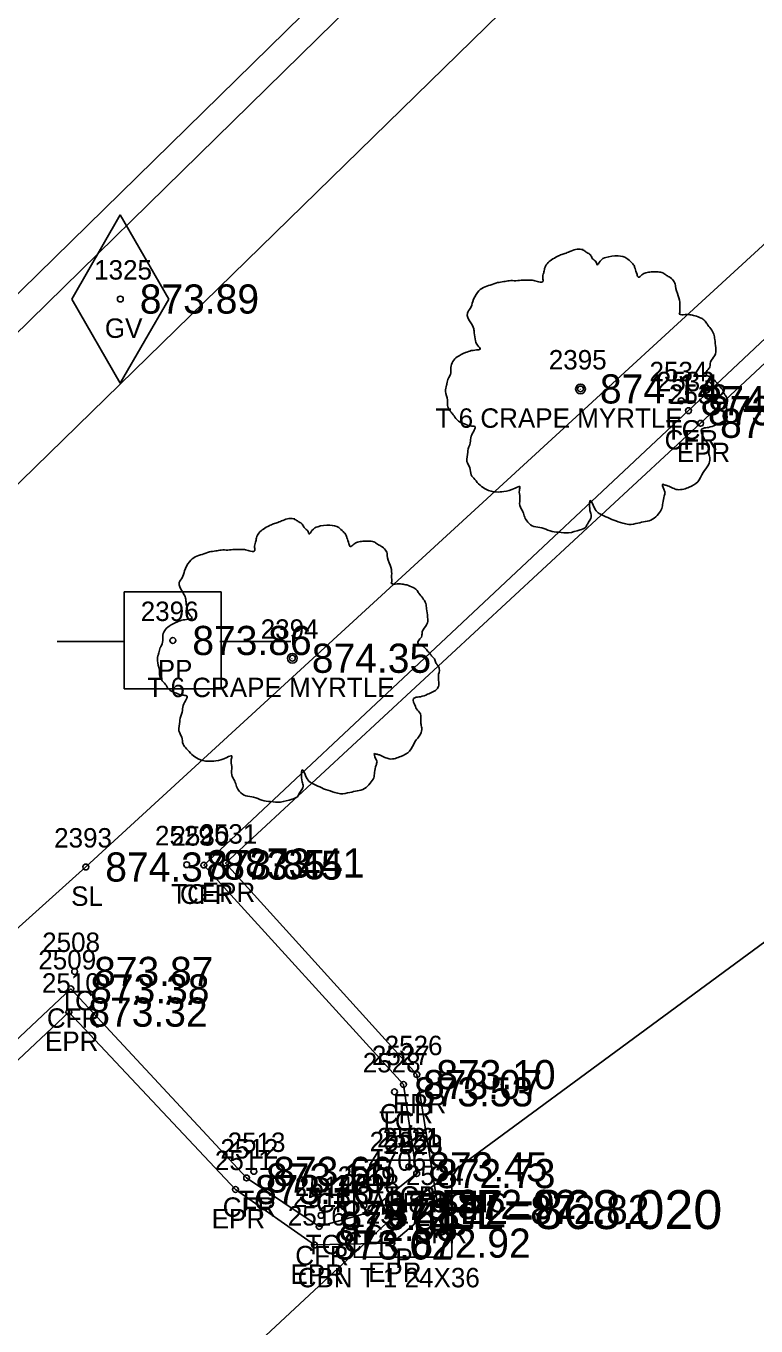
# Model space of a CAD drawing. Extents: x 1622501 to 1626664, y 1117816 to 1121579.
# Drawn here: x 1623806.5 to 1623844.1, y 1119016.9 to 1119083.8 of the extents above; entities that cross this region are included whole.
import ezdxf

# ---------------------------------------------------------------- set-up
doc = ezdxf.new("R2010")
doc.units = 0
for name, color, linetype in [('RD_EX_Conc', 7, 'Continuous'), ('RD_EX_Conc_txCode', 7, 'Continuous'), ('RD_EX_DR_Inlet', 7, 'Continuous'), ('RD_EX_DR_Inlet_txCode', 7, 'Continuous'), ('RD_EX_DR_Pipe', 7, 'Continuous'), ('RD_EX_DR_Pipe_txCode', 7, 'Continuous'), ('RD_EX_Road', 7, 'Continuous'), ('RD_EX_Road_txCode', 7, 'Continuous'), ('RD_EX_TX_Conc_ELEV', 7, 'Continuous'), ('RD_EX_TX_DR_Inlet_ELEV', 7, 'Continuous'), ('RD_EX_TX_Road_ELEV', 7, 'Continuous'), ('RD_EX_TX_UT_ELEV', 7, 'Continuous'), ('RD_EX_TX_VEG_ELEV', 7, 'Continuous'), ('RD_EX_UT', 7, 'Continuous'), ('RD_EX_UT_txCode', 7, 'Continuous'), ('RD_EX_VEG', 7, 'Continuous'), ('RD_EX_VEG_txCode', 7, 'Continuous'), ('RD_HC_Survey_ELEV', 7, 'Continuous'), ('RD_SMD_Locator', 7, 'Continuous'), ('RD_TX_Pipe_ElevEX', 7, 'Continuous')]:
    doc.layers.add(name, color=color, linetype=linetype)

msp = doc.modelspace()

# ---------------------------------------------------------------- linework, layer by layer
at = {"layer": 'RD_EX_Conc'}
for points in [[(1623723.663, 1118851.276), (1623685.686, 1118891.781), (1623680.278, 1118899.276), (1623678.543, 1118902.667), (1623678.543, 1118902.667), (1623675.573, 1118911.952), (1623675.054, 1118920.354), (1623676.566, 1118930.331), (1623679.225, 1118937.184), (1623684.435, 1118944.641), (1623689.976, 1118950.418), (1623724.501, 1118984.8), (1623759.009, 1119020.42), (1623793.698, 1119055.906), (1623829.35, 1119090.862), (1623865.612, 1119125.129), (1623901.916, 1119159.181), (1623933.224, 1119188.498)], [(1623676.299, 1118912.014), (1623681.213, 1118913.011), (1623680.576, 1118920.41), (1623681.86, 1118928.773), (1623684.243, 1118934.734), (1623688.548, 1118940.788), (1623694.147, 1118946.67), (1623728.265, 1118980.628), (1623762.622, 1119016.068), (1623797.565, 1119051.919), (1623833.104, 1119086.631), (1623869.148, 1119120.8), (1623905.547, 1119154.999), (1623936.969, 1119184.346), (1623933.79, 1119188.026)], [(1623776.374, 1119003.735), (1623808.841, 1119034.289), (1623817.882, 1119024.564), (1623821.612, 1119022.069), (1623824.094, 1119022.765), (1623826.626, 1119024.788), (1623826.626, 1119024.788), (1623825.953, 1119029.369), (1623815.684, 1119040.66), (1623840.6, 1119064.039), (1623868.084, 1119089.909)]]:
    msp.add_lwpolyline(points, dxfattribs=at)
at = {"layer": 'RD_EX_DR_Inlet'}
msp.add_line((1623828.428, 1119020.482), (1623828.428, 1119025.482), dxfattribs=at)
msp.add_lwpolyline([(1623828.428, 1119020.482), (1623828.428, 1119025.482), (1623823.428, 1119025.482), (1623823.428, 1119020.482)], close=True, dxfattribs=at)
at = {"layer": 'RD_EX_DR_Pipe'}
msp.add_lwpolyline([(1623764.491, 1118919.853), (1623773.64, 1118974.335), (1623825.837, 1119022.936), (1623907.44, 1119083.04), (1623936.884, 1119056.765)], dxfattribs=at)
at = {"layer": 'RD_EX_Road'}
for points in [[(1623722.97, 1118850.612), (1623684.945, 1118891.225), (1623679.413, 1118898.675), (1623674.261, 1118911.526), (1623673.503, 1118920.185), (1623675.206, 1118930.826), (1623677.985, 1118937.822), (1623683.61, 1118945.518), (1623688.806, 1118951.265), (1623723.469, 1118985.717), (1623758.003, 1119021.43), (1623792.693, 1119056.92), (1623828.408, 1119091.915), (1623864.599, 1119126.191), (1623900.882, 1119160.216), (1623932.37, 1119189.416), (1623932.628, 1119189.219), (1623935.818, 1119192.17), (1623973.771, 1119227.767), (1623990.875, 1119243.538), (1624009.987, 1119262.018), (1624046.295, 1119296.153)], [(1623776.805, 1119003.039), (1623808.744, 1119033.096), (1623817.315, 1119023.967), (1623821.371, 1119021.115), (1623825.354, 1119021.212), (1623827.704, 1119023.202), (1623826.634, 1119029.88), (1623816.804, 1119040.763), (1623841.225, 1119063.389), (1623868.182, 1119088.58)]]:
    msp.add_lwpolyline(points, dxfattribs=at)
at = {"layer": 'RD_EX_UT'}
for p, q in [((1623808.89, 1119069.782), (1623811.39, 1119074.112)), ((1623811.39, 1119074.112), (1623813.89, 1119069.782)), ((1623808.89, 1119069.782), (1623811.39, 1119065.452)), ((1623811.39, 1119065.452), (1623813.89, 1119069.782)), ((1623816.582, 1119054.725), (1623811.582, 1119054.725)), ((1623811.582, 1119054.725), (1623811.582, 1119049.725)), ((1623816.582, 1119049.725), (1623816.582, 1119054.725)), ((1623808.151, 1119052.163), (1623811.621, 1119052.163)), ((1623816.511, 1119052.163), (1623820.151, 1119052.163)), ((1623811.582, 1119049.725), (1623816.582, 1119049.725))]:
    msp.add_line(p, q, dxfattribs=at)
at = {"layer": 'RD_EX_VEG'}
msp.add_lwpolyline([(1623719.641, 1118895.843), (1623705.963, 1118915.58), (1623701.704, 1118941.089), (1623733.735, 1118974.045), (1623762.596, 1118998.968), (1623764.149, 1118997.606), (1623773.667, 1119008.214), (1623809.616, 1119040.562), (1623866.904, 1119093.207), (1623868.266, 1119096.09), (1623881.794, 1119107.882), (1623919.645, 1119143.849), (1623945.126, 1119165.729), (1623961.583, 1119122.835), (1623970.119, 1119088.038)], dxfattribs=at)
for centre, radius in [((1623835.049, 1119065.157), 0.25), ((1623835.037, 1119065.138), 0.0001), ((1623820.236, 1119051.301), 0.25), ((1623820.223, 1119051.282), 0.0001)]:
    msp.add_circle(centre, radius, dxfattribs=at)
for points in [[(1623835.181, 1119072.324), (1623834.881, 1119072.349), (1623834.557, 1119072.249), (1623834.307, 1119072.149), (1623834.082, 1119072.074), (1623833.857, 1119071.974), (1623833.557, 1119071.799), (1623833.332, 1119071.599), (1623833.207, 1119071.349), (1623833.157, 1119071.124), (1623833.107, 1119070.85), (1623833.107, 1119070.675), (1623832.982, 1119070.65), (1623832.832, 1119070.675), (1623832.582, 1119070.75), (1623832.333, 1119070.75), (1623832.083, 1119070.75), (1623831.733, 1119070.725), (1623831.383, 1119070.725), (1623831.108, 1119070.675), (1623830.783, 1119070.625), (1623830.408, 1119070.5), (1623830.059, 1119070.375), (1623829.759, 1119070.125), (1623829.509, 1119069.65), (1623829.384, 1119069.3), (1623829.234, 1119069.05), (1623829.384, 1119068.601), (1623829.559, 1119068.251), (1623829.584, 1119068.051), (1623829.659, 1119067.626), (1623829.759, 1119067.401), (1623829.884, 1119067.201), (1623829.809, 1119067.176), (1623829.434, 1119067.126), (1623829.134, 1119067.026), (1623828.709, 1119066.801), (1623828.484, 1119066.576), (1623828.384, 1119066.251), (1623828.359, 1119065.902), (1623828.259, 1119065.702), (1623828.184, 1119065.427), (1623828.159, 1119065.352), (1623828.109, 1119065.027), (1623828.209, 1119064.577), (1623828.234, 1119064.227), (1623828.359, 1119064.002), (1623828.509, 1119063.828), (1623828.684, 1119063.578), (1623829.084, 1119063.353), (1623829.409, 1119063.253), (1623829.609, 1119063.228), (1623829.434, 1119062.728), (1623829.384, 1119062.378), (1623829.259, 1119061.978), (1623829.259, 1119061.903), (1623829.209, 1119061.429), (1623829.359, 1119061.104), (1623829.434, 1119060.729), (1623829.609, 1119060.504), (1623829.884, 1119060.204), (1623830.208, 1119059.979), (1623830.708, 1119059.854), (1623831.108, 1119059.879), (1623831.683, 1119060.054), (1623831.933, 1119060.129), (1623831.908, 1119059.954), (1623831.933, 1119059.579), (1623831.933, 1119059.155), (1623832.083, 1119058.83), (1623832.183, 1119058.555), (1623832.333, 1119058.305), (1623832.657, 1119058.08), (1623833.057, 1119058.005), (1623833.482, 1119057.855), (1623833.932, 1119057.78), (1623834.432, 1119057.755), (1623835.031, 1119057.905), (1623835.306, 1119058.03), (1623835.406, 1119058.205), (1623835.606, 1119058.58), (1623835.556, 1119058.805), (1623835.581, 1119059.405), (1623835.681, 1119059.23), (1623835.856, 1119058.88), (1623836.356, 1119058.58), (1623836.756, 1119058.405), (1623837.23, 1119058.255), (1623837.53, 1119058.18), (1623838.005, 1119058.255), (1623838.38, 1119058.33), (1623838.755, 1119058.455), (1623839.055, 1119058.73), (1623839.23, 1119059.005), (1623839.28, 1119059.28), (1623839.354, 1119059.654), (1623839.404, 1119059.829)], [(1623839.404, 1119059.829), (1623839.33, 1119060.004), (1623839.28, 1119060.254), (1623839.354, 1119060.229), (1623839.529, 1119060.179), (1623839.804, 1119060.054), (1623840.029, 1119059.979), (1623840.354, 1119060.004), (1623840.629, 1119060.104), (1623841.079, 1119060.379), (1623841.354, 1119060.854), (1623841.628, 1119061.254), (1623841.703, 1119061.579), (1623841.653, 1119061.803), (1623841.628, 1119062.303), (1623841.429, 1119062.553), (1623841.379, 1119062.678), (1623841.279, 1119063.078), (1623841.354, 1119063.128), (1623841.628, 1119063.178), (1623842.003, 1119063.303), (1623842.278, 1119063.428), (1623842.503, 1119063.603), (1623842.578, 1119063.828), (1623842.553, 1119064.227), (1623842.603, 1119064.627), (1623842.528, 1119064.777), (1623842.428, 1119064.927), (1623842.353, 1119065.127), (1623842.203, 1119065.277), (1623842.103, 1119065.427), (1623842.003, 1119065.527), (1623841.878, 1119065.677), (1623841.703, 1119065.802), (1623841.554, 1119065.852), (1623841.504, 1119066.002), (1623841.653, 1119066.202), (1623841.703, 1119066.301), (1623841.728, 1119066.526), (1623841.953, 1119066.876), (1623842.003, 1119067.276), (1623841.953, 1119067.701), (1623841.903, 1119067.976), (1623841.753, 1119068.251), (1623841.554, 1119068.501), (1623841.429, 1119068.675), (1623841.254, 1119068.8), (1623840.929, 1119068.925), (1623840.679, 1119068.975), (1623840.329, 1119068.975), (1623840.129, 1119069.025), (1623840.154, 1119069.075), (1623840.154, 1119069.225), (1623840.154, 1119069.5), (1623840.079, 1119069.95), (1623839.929, 1119070.45), (1623839.929, 1119070.475), (1623839.829, 1119070.725), (1623839.604, 1119070.924), (1623839.429, 1119071.024), (1623839.23, 1119071.149), (1623838.98, 1119071.174), (1623838.68, 1119071.174), (1623838.405, 1119071.124), (1623838.205, 1119071.024), (1623838.03, 1119070.899), (1623837.955, 1119071.049), (1623837.855, 1119071.349), (1623837.805, 1119071.499), (1623837.655, 1119071.674), (1623837.43, 1119071.874), (1623836.98, 1119071.999), (1623836.356, 1119071.924), (1623836.056, 1119071.724), (1623835.906, 1119071.549), (1623835.856, 1119071.674), (1623835.656, 1119071.874), (1623835.556, 1119072.049), (1623835.381, 1119072.174), (1623835.231, 1119072.274), (1623835.131, 1119072.324)], [(1623820.368, 1119058.468), (1623820.068, 1119058.493), (1623819.743, 1119058.393), (1623819.493, 1119058.293), (1623819.268, 1119058.218), (1623819.044, 1119058.118), (1623818.744, 1119057.944), (1623818.519, 1119057.744), (1623818.394, 1119057.494), (1623818.344, 1119057.269), (1623818.294, 1119056.994), (1623818.294, 1119056.819), (1623818.169, 1119056.794), (1623818.019, 1119056.819), (1623817.769, 1119056.894), (1623817.519, 1119056.894), (1623817.269, 1119056.894), (1623816.919, 1119056.869), (1623816.57, 1119056.869), (1623816.295, 1119056.819), (1623815.97, 1119056.769), (1623815.595, 1119056.644), (1623815.245, 1119056.519), (1623814.945, 1119056.269), (1623814.695, 1119055.795), (1623814.57, 1119055.445), (1623814.421, 1119055.195), (1623814.57, 1119054.745), (1623814.745, 1119054.395), (1623814.77, 1119054.195), (1623814.845, 1119053.77), (1623814.945, 1119053.546), (1623815.07, 1119053.346), (1623814.995, 1119053.321), (1623814.62, 1119053.271), (1623814.321, 1119053.171), (1623813.896, 1119052.946), (1623813.671, 1119052.721), (1623813.571, 1119052.396), (1623813.546, 1119052.046), (1623813.446, 1119051.846), (1623813.371, 1119051.571), (1623813.346, 1119051.496), (1623813.296, 1119051.172), (1623813.396, 1119050.722), (1623813.421, 1119050.372), (1623813.546, 1119050.147), (1623813.696, 1119049.972), (1623813.871, 1119049.722), (1623814.271, 1119049.497), (1623814.595, 1119049.397), (1623814.795, 1119049.372), (1623814.62, 1119048.873), (1623814.57, 1119048.523), (1623814.446, 1119048.123), (1623814.446, 1119048.048), (1623814.396, 1119047.573), (1623814.545, 1119047.248), (1623814.62, 1119046.873), (1623814.795, 1119046.649), (1623815.07, 1119046.349), (1623815.395, 1119046.124), (1623815.895, 1119045.999), (1623816.295, 1119046.024), (1623816.87, 1119046.199), (1623817.119, 1119046.274), (1623817.094, 1119046.099), (1623817.119, 1119045.724), (1623817.119, 1119045.299), (1623817.269, 1119044.974), (1623817.369, 1119044.699), (1623817.519, 1119044.449), (1623817.844, 1119044.225), (1623818.244, 1119044.15), (1623818.669, 1119044), (1623819.119, 1119043.925), (1623819.618, 1119043.9), (1623820.218, 1119044.05), (1623820.493, 1119044.175), (1623820.593, 1119044.35), (1623820.793, 1119044.724), (1623820.743, 1119044.949), (1623820.768, 1119045.549), (1623820.868, 1119045.374), (1623821.043, 1119045.024), (1623821.542, 1119044.724), (1623821.942, 1119044.549), (1623822.417, 1119044.399), (1623822.717, 1119044.325), (1623823.192, 1119044.399), (1623823.567, 1119044.474), (1623823.941, 1119044.599), (1623824.241, 1119044.874), (1623824.416, 1119045.149), (1623824.466, 1119045.424), (1623824.541, 1119045.799), (1623824.591, 1119045.974)], [(1623824.591, 1119045.974), (1623824.516, 1119046.149), (1623824.466, 1119046.399), (1623824.541, 1119046.374), (1623824.716, 1119046.324), (1623824.991, 1119046.199), (1623825.216, 1119046.124), (1623825.541, 1119046.149), (1623825.816, 1119046.249), (1623826.265, 1119046.524), (1623826.54, 1119046.998), (1623826.815, 1119047.398), (1623826.89, 1119047.723), (1623826.84, 1119047.948), (1623826.815, 1119048.448), (1623826.615, 1119048.698), (1623826.565, 1119048.823), (1623826.465, 1119049.222), (1623826.54, 1119049.272), (1623826.815, 1119049.322), (1623827.19, 1119049.447), (1623827.465, 1119049.572), (1623827.69, 1119049.747), (1623827.765, 1119049.972), (1623827.74, 1119050.372), (1623827.79, 1119050.772), (1623827.715, 1119050.922), (1623827.615, 1119051.072), (1623827.54, 1119051.272), (1623827.39, 1119051.421), (1623827.29, 1119051.571), (1623827.19, 1119051.671), (1623827.065, 1119051.821), (1623826.89, 1119051.946), (1623826.74, 1119051.996), (1623826.69, 1119052.146), (1623826.84, 1119052.346), (1623826.89, 1119052.446), (1623826.915, 1119052.671), (1623827.14, 1119053.021), (1623827.19, 1119053.421), (1623827.14, 1119053.845), (1623827.09, 1119054.12), (1623826.94, 1119054.395), (1623826.74, 1119054.645), (1623826.615, 1119054.82), (1623826.44, 1119054.945), (1623826.115, 1119055.07), (1623825.866, 1119055.12), (1623825.516, 1119055.12), (1623825.316, 1119055.17), (1623825.341, 1119055.22), (1623825.341, 1119055.37), (1623825.341, 1119055.645), (1623825.266, 1119056.094), (1623825.116, 1119056.594), (1623825.116, 1119056.619), (1623825.016, 1119056.869), (1623824.791, 1119057.069), (1623824.616, 1119057.169), (1623824.416, 1119057.294), (1623824.166, 1119057.319), (1623823.866, 1119057.319), (1623823.592, 1119057.269), (1623823.392, 1119057.169), (1623823.217, 1119057.044), (1623823.142, 1119057.194), (1623823.042, 1119057.494), (1623822.992, 1119057.644), (1623822.842, 1119057.819), (1623822.617, 1119058.019), (1623822.167, 1119058.143), (1623821.542, 1119058.069), (1623821.243, 1119057.869), (1623821.093, 1119057.694), (1623821.043, 1119057.819), (1623820.843, 1119058.019), (1623820.743, 1119058.193), (1623820.568, 1119058.318), (1623820.418, 1119058.418), (1623820.318, 1119058.468)]]:
    msp.add_spline(points, degree=3, dxfattribs=at)
at = {"layer": 'RD_SMD_Locator'}
for centre, radius in [((1623811.39, 1119069.782), 0.15), ((1623835.049, 1119065.157), 0.15), ((1623840.227, 1119064.551), 0.15), ((1623840.6, 1119064.039), 0.15), ((1623841.225, 1119063.389), 0.15), ((1623814.092, 1119052.216), 0.15), ((1623820.236, 1119051.301), 0.15), ((1623809.616, 1119040.562), 0.15), ((1623814.802, 1119040.678), 0.15), ((1623815.684, 1119040.66), 0.15), ((1623816.804, 1119040.763), 0.15), ((1623809.041, 1119035.189), 0.15), ((1623808.841, 1119034.289), 0.15), ((1623808.744, 1119033.096), 0.15), ((1623826.634, 1119029.88), 0.15), ((1623825.483, 1119028.995), 0.15), ((1623825.953, 1119029.369), 0.15), ((1623818.252, 1119024.901), 0.15), ((1623826.222, 1119025.136), 0.15), ((1623826.222, 1119025.136), 0.15), ((1623817.882, 1119024.564), 0.15), ((1623826.626, 1119024.788), 0.15), ((1623826.626, 1119024.788), 0.15), ((1623817.315, 1119023.967), 0.15), ((1623823.912, 1119023.156), 0.15), ((1623825.837, 1119022.936), 0.2), ((1623825.837, 1119022.936), 0.15), ((1623827.704, 1119023.202), 0.15), ((1623821.71, 1119022.638), 0.15), ((1623824.094, 1119022.765), 0.15), ((1623821.612, 1119022.069), 0.15), ((1623821.371, 1119021.115), 0.15), ((1623825.354, 1119021.212), 0.15)]:
    msp.add_circle(centre, radius, dxfattribs=at)

# ---------------------------------------------------------------- texts
at = {"layer": 'RD_EX_Conc_txCode'}
for s, p in [('2534', (1623838.597, 1119065.551)), ('2533', (1623838.97, 1119065.039)), ('TC', (1623839.432, 1119062.551)), ('CFR', (1623839.372, 1119062.039)), ('2529', (1623813.172, 1119041.678)), ('2530', (1623814.015, 1119041.66)), ('TC', (1623814.006, 1119038.678)), ('CFR', (1623814.456, 1119038.66)), ('2508', (1623807.372, 1119036.189)), ('2509', (1623807.172, 1119035.289)), ('TC', (1623808.246, 1119033.189)), ('CFR', (1623807.613, 1119032.289)), ('2527', (1623824.323, 1119030.369)), ('2528', (1623823.853, 1119029.995)), ('CFR', (1623824.724, 1119027.369)), ('TC', (1623824.687, 1119026.995)), ('2522', (1623824.592, 1119026.136)), ('2521', (1623824.875, 1119026.136)), ('2512', (1623816.536, 1119025.564)), ('2513', (1623816.906, 1119025.901)), ('2520', (1623824.957, 1119025.788)), ('2523', (1623824.996, 1119025.788)), ('2519', (1623822.565, 1119024.156)), ('2514', (1623820.364, 1119023.638)), ('2518', (1623822.748, 1119023.765)), ('TC', (1623817.457, 1119022.901)), ('2515', (1623820.266, 1119023.069)), ('CFRA 18 CONC', (1623821.453, 1119022.788)), ('TCA', (1623824.938, 1119023.136)), ('TCB', (1623824.954, 1119023.136)), ('CFRB', (1623824.926, 1119022.788)), ('CFR', (1623816.654, 1119022.564)), ('CFR', (1623822.866, 1119020.765)), ('TC', (1623823.116, 1119021.156)), ('CFR', (1623820.384, 1119020.069)), ('TC', (1623820.915, 1119020.638))]:
    msp.add_text(s, height=1, dxfattribs=at).set_placement(p)
at = {"layer": 'RD_EX_DR_Inlet_txCode'}
for s, p in [('2525', (1623824.207, 1119025.936)), ('CBN T 1 24X36', (1623820.506, 1119018.936))]:
    msp.add_text(s, height=1, dxfattribs=at).set_placement(p)
at = {"layer": 'RD_EX_DR_Pipe_txCode'}
for s, p in [('4706', (1623824.144, 1119024.936)), ('P', (1623825.53, 1119019.936))]:
    msp.add_text(s, height=1, dxfattribs=at).set_placement(p)
at = {"layer": 'RD_EX_Road_txCode'}
for s, p in [('2532', (1623839.595, 1119064.389)), ('EPR', (1623839.997, 1119061.389)), ('2531', (1623815.458, 1119041.763)), ('EPR', (1623815.576, 1119038.763)), ('2510', (1623807.358, 1119034.096)), ('EPR', (1623807.515, 1119031.096)), ('2526', (1623824.98, 1119030.88)), ('EPR', (1623825.405, 1119027.88)), ('2511', (1623816.252, 1119024.967)), ('2524', (1623826.074, 1119024.202)), ('2516', (1623820, 1119022.115)), ('2517', (1623824.008, 1119022.212)), ('EPR', (1623816.087, 1119021.967)), ('EPR', (1623826.475, 1119021.202)), ('EPR', (1623820.142, 1119019.115)), ('EPR', (1623824.126, 1119019.212))]:
    msp.add_text(s, height=1, dxfattribs=at).set_placement(p)
at = {"layer": 'RD_EX_TX_Conc_ELEV'}
for s, p in [('874.21', (1623841.227, 1119063.801)), ('873.73', (1623841.6, 1119063.289)), ('873.85', (1623815.802, 1119039.928)), ('873.45', (1623816.684, 1119039.91)), ('873.87', (1623810.041, 1119034.439)), ('873.38', (1623809.841, 1119033.539)), ('873.53', (1623826.483, 1119028.245)), ('873.07', (1623826.953, 1119028.619)), ('873.45', (1623827.222, 1119024.386)), ('873.45', (1623827.222, 1119024.386)), ('873.16', (1623818.882, 1119023.814)), ('873.66', (1623819.252, 1119024.151)), ('872.73', (1623827.626, 1119024.038)), ('872.73', (1623827.626, 1119024.038)), ('873.47', (1623824.912, 1119022.406)), ('873.48', (1623822.71, 1119021.888)), ('872.72', (1623825.094, 1119022.015)), ('872.98', (1623822.612, 1119021.319))]:
    msp.add_text(s, height=1.5, dxfattribs=at).set_placement(p)
at = {"layer": 'RD_EX_TX_DR_Inlet_ELEV'}
msp.add_text('EL=872.82', height=1.5, dxfattribs=at).set_placement((1623828.837, 1119022.186))
at = {"layer": 'RD_EX_TX_Road_ELEV'}
for s, p in [('873.73', (1623842.225, 1119062.639)), ('873.41', (1623817.804, 1119040.013)), ('873.32', (1623809.744, 1119032.346)), ('873.10', (1623827.634, 1119029.13)), ('873.16', (1623818.315, 1119023.217)), ('872.92', (1623828.704, 1119022.452)), ('873.02', (1623822.371, 1119020.365)), ('872.92', (1623826.354, 1119020.462))]:
    msp.add_text(s, height=1.5, dxfattribs=at).set_placement(p)
at = {"layer": 'RD_EX_TX_UT_ELEV'}
msp.add_text('873.89', height=1.5, dxfattribs=at).set_placement((1623812.39, 1119069.032))
at = {"layer": 'RD_EX_TX_VEG_ELEV'}
for s, p in [('874.14', (1623836.049, 1119064.407)), ('874.35', (1623821.236, 1119050.551)), ('874.37', (1623810.616, 1119039.812))]:
    msp.add_text(s, height=1.5, dxfattribs=at).set_placement(p)
at = {"layer": 'RD_EX_UT_txCode'}
for s, p in [('1325', (1623810.043, 1119070.782)), ('GV', (1623810.595, 1119067.782)), ('2396', (1623812.438, 1119053.216)), ('PP', (1623813.312, 1119050.216))]:
    msp.add_text(s, height=1, dxfattribs=at).set_placement(p)
at = {"layer": 'RD_EX_VEG_txCode'}
for s, p in [('2395', (1623833.419, 1119066.157)), ('T 6 CRAPE MYRTLE', (1623827.597, 1119063.157)), ('2394', (1623818.606, 1119052.301)), ('T 6 CRAPE MYRTLE', (1623812.783, 1119049.301)), ('2393', (1623807.986, 1119041.562)), ('SL', (1623808.86, 1119038.562))]:
    msp.add_text(s, height=1, dxfattribs=at).set_placement(p)
at = {"layer": 'RD_HC_Survey_ELEV'}
msp.add_text('873.86', height=1.5, dxfattribs=at).set_placement((1623815.092, 1119051.466))
at = {"layer": 'RD_TX_Pipe_ElevEX'}
msp.add_text('EL=868.020', height=2, dxfattribs=at).set_placement((1623827.837, 1119021.936))

doc.saveas('drawing.dxf')
